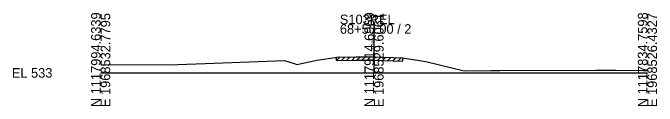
# Model space of a CAD drawing. Extents: x -26 to 163, y -10 to 24518.
# Drawn here: x -25.7 to 162.8, y 16990.3 to 17017.5 of the extents above; entities that cross this region are included whole.
import ezdxf

# ---------------------------------------------------------------- set-up
doc = ezdxf.new("R2010")
doc.units = 0
for name, color, linetype in [('RD_GPK_XS_Cell', 7, 'Continuous'), ('RD_XS_ExGround', 7, 'Continuous'), ('RD_XS_ExPaveRet', 7, 'Continuous'), ('RD_XS_TX_Elev_EX', 7, 'Continuous')]:
    doc.layers.add(name, color=color, linetype=linetype)

msp = doc.modelspace()

# ---------------------------------------------------------------- linework, layer by layer
at = {"layer": 'RD_GPK_XS_Cell'}
for p, q in [((80, 17000), (80, 17014.23)), ((0, 17000), (80, 17000)), ((80, 17000), (160, 17000))]:
    msp.add_line(p, q, dxfattribs=at)
at = {"layer": 'RD_XS_ExGround'}
msp.add_lwpolyline([(0, 17002.45), (21.11, 17002.4), (22.61, 17002.46), (30.6, 17002.76), (53.84, 17003.63), (56.94, 17002.63), (57.45, 17002.48), (62.41, 17003.54), (63.23, 17003.71), (68.62, 17004.53), (68.97, 17004.58), (74.8, 17004.68), (78.41, 17004.74), (80, 17004.69), (88.37, 17004.41), (95.11, 17003.32), (106.36, 17000.64), (114.19, 17000.7), (116.83, 17000.7), (144.92, 17000.79), (150.74, 17000.78), (158.78, 17000.7), (160, 17000.69)], dxfattribs=at)
at = {"layer": 'RD_XS_ExPaveRet'}
for p, q in [((68.97, 17003.58), (69.99, 17004.6)), ((68.97, 17003.58), (68.97, 17004.58)), ((70.47, 17003.61), (71.49, 17004.62)), ((71.97, 17003.63), (72.99, 17004.65)), ((73.47, 17003.66), (74.49, 17004.67)), ((74.97, 17003.68), (75.99, 17004.7)), ((76.47, 17003.71), (77.49, 17004.73)), ((77.97, 17003.74), (78.96, 17004.72)), ((79.47, 17003.71), (80.44, 17004.68)), ((80.97, 17003.66), (81.94, 17004.63)), ((82.47, 17003.61), (83.44, 17004.58)), ((83.97, 17003.56), (84.94, 17004.53)), ((85.47, 17003.51), (86.44, 17004.48)), ((86.97, 17003.46), (87.94, 17004.43)), ((88.37, 17004.41), (88.37, 17003.41)), ((68.97, 17003.58), (74.8, 17003.68)), ((74.8, 17003.68), (78.41, 17003.74)), ((78.41, 17003.74), (80, 17003.69)), ((80, 17003.69), (88.37, 17003.41))]:
    msp.add_line(p, q, dxfattribs=at)

# ---------------------------------------------------------------- texts
at = {"layer": 'RD_GPK_XS_Cell'}
for s, p in [('N 1117994.6339', (0, 16990)), ('E 1968532.7795', (2.8, 16990)), ('N 1117914.6969', (80, 16990)), ('E 1968529.6061', (82.8, 16990)), ('N 1117834.7598', (160, 16990)), ('E 1968526.4327', (162.8, 16990))]:
    msp.add_text(s, height=2.8, rotation=90, dxfattribs=at).set_placement(p)
for s, p in [('S103REL', (70, 17014.23)), ('68+50.00 / 2', (70, 17011.43)), ('EL 533', (-26, 16998.6))]:
    msp.add_text(s, height=2.8, dxfattribs=at).set_placement(p)
at = {"layer": 'RD_XS_TX_Elev_EX'}
msp.add_text('537.69', height=0.8, rotation=90, dxfattribs=at).set_placement((79.9, 17006.69))

doc.saveas('drawing.dxf')
